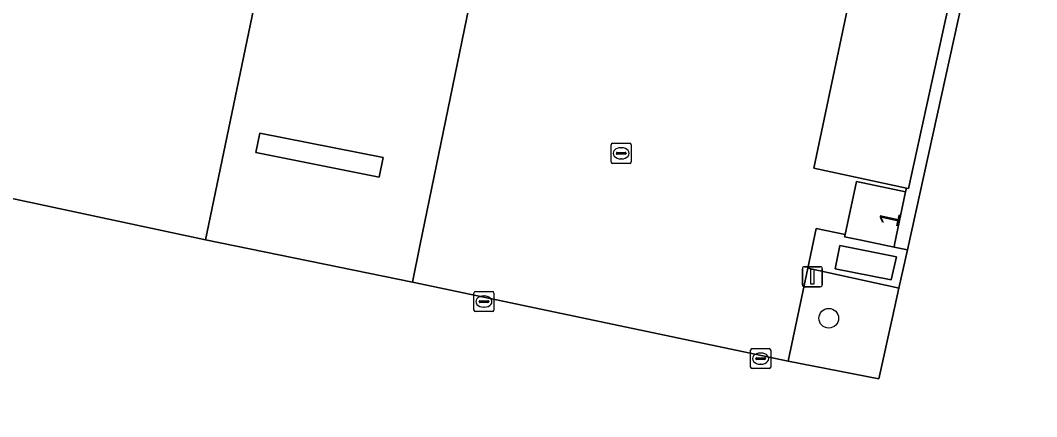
# Model space of a CAD drawing. Extents: x 157692 to 159674, y 381452 to 383291.
# Drawn here: x 158157 to 158207.7, y 382127.2 to 382147 of the extents above; entities that cross this region are included whole.
import ezdxf

# ---------------------------------------------------------------- set-up
doc = ezdxf.new("R2010")
doc.units = 0
for name, color, linetype in [('IMGEO_Boom', 7, 'Continuous'), ('IMGEO_Erf', 7, 'Continuous'), ('IMGEO_Groenvoorziening', 7, 'Continuous'), ('IMGEO_Kolk', 7, 'Continuous'), ('IMGEO_Lage_trafo', 7, 'Continuous'), ('IMGEO_Lichtmast', 7, 'Continuous'), ('IMGEO_Pand', 7, 'Continuous'), ('IMGEO_Pand_nummerreeks', 7, 'Continuous'), ('IMGEO_Parkeervlak_open', 7, 'Continuous'), ('IMGEO_Rijbaan_lokaal_gesloten', 7, 'Continuous'), ('IMGEO_Rijbaan_lokaal_open', 7, 'Continuous'), ('IMGEO_Voetpad_gesloten', 7, 'Continuous'), ('IMGEO_Voetpad_halfverhard', 7, 'Continuous')]:
    doc.layers.add(name, color=color, linetype=linetype)

msp = doc.modelspace()

# ---------------------------------------------------------------- linework, layer by layer
at = {"layer": 'IMGEO_Boom'}
msp.add_circle((158197.339, 382132.128), 0.489, dxfattribs=at)
at = {"layer": 'IMGEO_Erf'}
msp.add_lwpolyline([(158219.414, 382155.844), (158206.316, 382158.502), (158201.257, 382135.532), (158200.838, 382133.629), (158200.517, 382132.175), (158199.841, 382129.108), (158199.834, 382129.109), (158195.31, 382129.992), (158176.587, 382133.918), (158166.278, 382136.044), (158154.599, 382138.529), (158137.162, 382053.571), (158133.419, 382037.075), (158130.551, 382022.604), (158125.897, 382000), (158121.713, 381979.263), (158120.644, 381974.489), (158119.054, 381966.712)], dxfattribs=at)
at = {"layer": 'IMGEO_Groenvoorziening'}
msp.add_lwpolyline([(158206.316, 382158.502), (158206.19, 382158.527), (158205.717, 382158.623), (158205.666, 382158.371), (158203.138, 382146.94), (158201.307, 382138.595), (158201.211, 382138.616), (158201.17, 382138.423), (158200.619, 382135.81), (158200.591, 382135.679), (158200.927, 382135.605), (158201.257, 382135.532)], close=True, dxfattribs=at)
at = {"layer": 'IMGEO_Kolk'}
for p, q in [((158186.492, 382139.925), (158186.492, 382140.777)), ((158186.567, 382140.851), (158187.419, 382140.851)), ((158186.98, 382140.631), (158187.005, 382140.631)), ((158187.493, 382140.777), (158187.493, 382139.925)), ((158186.751, 382140.345), (158186.751, 382140.357)), ((158187.189, 382140.308), (158186.791, 382140.308)), ((158186.794, 382140.394), (158187.192, 382140.394)), ((158187.235, 382140.357), (158187.235, 382140.345)), ((158187.419, 382139.851), (158186.567, 382139.851)), ((158187.003, 382140.071), (158186.978, 382140.071)), ((158179.651, 382132.532), (158179.651, 382133.384)), ((158179.726, 382133.458), (158180.578, 382133.458)), ((158179.953, 382133.001), (158180.351, 382133.001)), ((158180.139, 382133.238), (158180.164, 382133.238)), ((158180.652, 382133.384), (158180.652, 382132.532)), ((158179.91, 382132.952), (158179.91, 382132.964)), ((158180.348, 382132.915), (158179.95, 382132.915)), ((158180.162, 382132.678), (158180.137, 382132.678)), ((158180.394, 382132.964), (158180.394, 382132.952)), ((158180.578, 382132.458), (158179.726, 382132.458)), ((158193.443, 382129.687), (158193.443, 382130.539)), ((158193.518, 382130.613), (158194.37, 382130.613)), ((158194.444, 382130.539), (158194.444, 382129.687)), ((158193.702, 382130.107), (158193.702, 382130.119)), ((158194.14, 382130.07), (158193.742, 382130.07)), ((158193.745, 382130.156), (158194.143, 382130.156)), ((158193.931, 382130.393), (158193.956, 382130.393)), ((158194.186, 382130.119), (158194.186, 382130.107)), ((158194.37, 382129.613), (158193.518, 382129.613)), ((158193.954, 382129.833), (158193.929, 382129.833))]:
    msp.add_line(p, q, dxfattribs=at)
for points in [[(158186.492, 382139.925), (158186.492, 382140.777)], [(158186.567, 382140.851), (158187.419, 382140.851)], [(158187.493, 382140.777), (158187.493, 382139.925)], [(158187.419, 382139.851), (158186.567, 382139.851)], [(158179.651, 382132.532), (158179.651, 382133.384)], [(158179.726, 382133.458), (158180.578, 382133.458)], [(158180.652, 382133.384), (158180.652, 382132.532)], [(158180.578, 382132.458), (158179.726, 382132.458)], [(158193.443, 382129.687), (158193.443, 382130.539)], [(158193.518, 382130.613), (158194.37, 382130.613)], [(158194.444, 382130.539), (158194.444, 382129.687)], [(158194.37, 382129.613), (158193.518, 382129.613)]]:
    msp.add_lwpolyline(points, dxfattribs=at)
for centre, radius, start, end in [((158186.569, 382140.775), 0.0765, 91.552, 178.448), ((158186.569, 382140.775), 0.0765, 91.552, 178.448), ((158187.417, 382140.775), 0.0765, 1.552, 88.448), ((158187.417, 382140.775), 0.0765, 1.552, 88.448), ((158186.791, 382140.354), 0.0403, 85.8775, 175.7526), ((158186.788, 382140.344), 0.0366, 178.938, 274.7102), ((158187.192, 382140.351), 0.043, 264.8664, 352.4533), ((158187.196, 382140.356), 0.0386, 1.7309, 96.639), ((158186.569, 382139.927), 0.0765, 181.552, 268.448), ((158186.569, 382139.927), 0.0765, 181.552, 268.448), ((158187.417, 382139.927), 0.0765, 271.552, 358.448), ((158187.417, 382139.927), 0.0765, 271.552, 358.448), ((158179.728, 382133.382), 0.0765, 91.552, 178.448), ((158179.728, 382133.382), 0.0765, 91.552, 178.448), ((158179.95, 382132.961), 0.0403, 85.8775, 175.7526), ((158180.355, 382132.963), 0.0386, 1.7309, 96.639), ((158180.576, 382133.382), 0.0765, 1.552, 88.448), ((158180.576, 382133.382), 0.0765, 1.552, 88.448), ((158179.728, 382132.534), 0.0765, 181.552, 268.448), ((158179.728, 382132.534), 0.0765, 181.552, 268.448), ((158179.947, 382132.951), 0.0366, 178.938, 274.7102), ((158180.351, 382132.958), 0.043, 264.8664, 352.4533), ((158180.576, 382132.534), 0.0765, 271.552, 358.448), ((158180.576, 382132.534), 0.0765, 271.552, 358.448), ((158193.52, 382130.537), 0.0765, 91.552, 178.448), ((158193.52, 382130.537), 0.0765, 91.552, 178.448), ((158194.368, 382130.537), 0.0765, 1.552, 88.448), ((158194.368, 382130.537), 0.0765, 1.552, 88.448), ((158193.742, 382130.116), 0.0403, 85.8775, 175.7526), ((158193.739, 382130.106), 0.0366, 178.938, 274.7102), ((158194.143, 382130.113), 0.043, 264.8664, 352.4533), ((158194.147, 382130.118), 0.0386, 1.7309, 96.639), ((158193.52, 382129.689), 0.0765, 181.552, 268.448), ((158193.52, 382129.689), 0.0765, 181.552, 268.448), ((158194.368, 382129.689), 0.0765, 271.552, 358.448), ((158194.368, 382129.689), 0.0765, 271.552, 358.448)]:
    msp.add_arc(centre, radius, start, end, dxfattribs=at)
for centre, major_axis, ratio, start_param, end_param in [((158186.979, 382140.351), (-0.387, 0.002), 0.722429, 4.712389, 7.853982), ((158187.004, 382140.351), (-0.39, 0.002), 0.717154, 1.570796, 4.712389), ((158180.138, 382132.958), (-0.387, 0.002), 0.722429, 4.712389, 7.853982), ((158180.163, 382132.958), (-0.39, 0.002), 0.717154, 1.570796, 4.712389), ((158193.93, 382130.113), (-0.387, 0.002), 0.722429, 4.712389, 7.853982), ((158193.955, 382130.113), (-0.39, 0.002), 0.717154, 1.570796, 4.712389)]:
    msp.add_ellipse(centre, major_axis=major_axis, ratio=ratio, start_param=start_param, end_param=end_param, dxfattribs=at)
at = {"layer": 'IMGEO_Lage_trafo'}
msp.add_lwpolyline([(158200.446, 382134.036), (158200.72, 382135.183), (158197.892, 382135.75), (158197.66, 382134.595)], close=True, dxfattribs=at)
at = {"layer": 'IMGEO_Lichtmast'}
for p, q in [((158196.025, 382133.797), (158196.025, 382134.597)), ((158196.025, 382134.597), (158196.025, 382133.797)), ((158196.125, 382134.697), (158196.915, 382134.697)), ((158196.915, 382134.697), (158196.125, 382134.697)), ((158197.015, 382134.597), (158197.015, 382133.797)), ((158197.015, 382133.797), (158197.015, 382134.597)), ((158196.915, 382133.697), (158196.125, 382133.697)), ((158196.125, 382133.697), (158196.915, 382133.697))]:
    msp.add_line(p, q, dxfattribs=at)
msp.add_lwpolyline([(158196.445, 382134.572), (158196.595, 382134.572), (158196.595, 382133.822), (158196.445, 382133.822), (158196.445, 382134.572)], dxfattribs=at)
for centre, start, end in [((158196.125, 382134.597), 90, 180), ((158196.125, 382134.597), 90, 180), ((158196.915, 382134.597), 0, 90), ((158196.915, 382134.597), 360, 90), ((158196.125, 382133.797), 180, 270), ((158196.125, 382133.797), 180, 270), ((158196.915, 382133.797), 270, 0), ((158196.915, 382133.797), 270, 0)]:
    msp.add_arc(centre, 0.1, start, end, dxfattribs=at)
at = {"layer": 'IMGEO_Pand'}
msp.add_lwpolyline([(158201.17, 382138.423), (158198.721, 382138.949), (158198.152, 382136.303), (158198.127, 382136.188), (158198.951, 382136.018), (158200.591, 382135.679), (158200.619, 382135.81)], close=True, dxfattribs=at)
at = {"layer": 'IMGEO_Parkeervlak_open'}
msp.add_lwpolyline([(158205.666, 382158.371), (158200.705, 382159.415), (158198.404, 382148.228), (158196.59, 382139.608), (158201.211, 382138.616), (158201.307, 382138.595), (158203.138, 382146.94)], close=True, dxfattribs=at)
at = {"layer": 'IMGEO_Rijbaan_lokaal_gesloten'}
for points in [[(158181.739, 382159.015), (158171.484, 382161.1), (158166.278, 382136.044), (158176.587, 382133.918), (158176.961, 382135.739)], [(158175.134, 382140.14), (158174.932, 382139.16), (158168.789, 382140.395), (158168.981, 382141.363)]]:
    msp.add_lwpolyline(points, close=True, dxfattribs=at)
at = {"layer": 'IMGEO_Rijbaan_lokaal_open'}
for points in [[(158157.48, 382152.512), (158156.939, 382149.808), (158154.599, 382138.529), (158166.278, 382136.044), (158171.484, 382161.1)], [(158185.972, 382158.164), (158181.739, 382159.015), (158176.961, 382135.739), (158176.587, 382133.918), (158195.31, 382129.992), (158196.295, 382134.63), (158196.712, 382136.595), (158198.152, 382136.303), (158198.721, 382138.949), (158201.17, 382138.423), (158201.211, 382138.616), (158196.59, 382139.608), (158198.404, 382148.228)]]:
    msp.add_lwpolyline(points, dxfattribs=at)
at = {"layer": 'IMGEO_Voetpad_gesloten'}
for points in [[(158168.981, 382141.363), (158168.789, 382140.395), (158174.932, 382139.16), (158175.134, 382140.14)], [(158201.257, 382135.532), (158200.927, 382135.605), (158200.591, 382135.679), (158198.951, 382136.018), (158198.127, 382136.188), (158198.152, 382136.303), (158196.712, 382136.595), (158196.295, 382134.63), (158200.694, 382133.661), (158200.838, 382133.629)], [(158200.446, 382134.036), (158197.66, 382134.595), (158197.892, 382135.75), (158200.72, 382135.183)]]:
    msp.add_lwpolyline(points, close=True, dxfattribs=at)
at = {"layer": 'IMGEO_Voetpad_halfverhard'}
msp.add_lwpolyline([(158200.838, 382133.629), (158200.694, 382133.661), (158196.295, 382134.63), (158195.31, 382129.992), (158199.834, 382129.109), (158199.841, 382129.108), (158200.517, 382132.175)], close=True, dxfattribs=at)

# ---------------------------------------------------------------- texts
at = {"layer": 'IMGEO_Pand_nummerreeks'}
msp.add_text('1', height=1, rotation=77.6644, dxfattribs=at).set_placement((158200.774, 382136.613))

doc.saveas('drawing.dxf')
